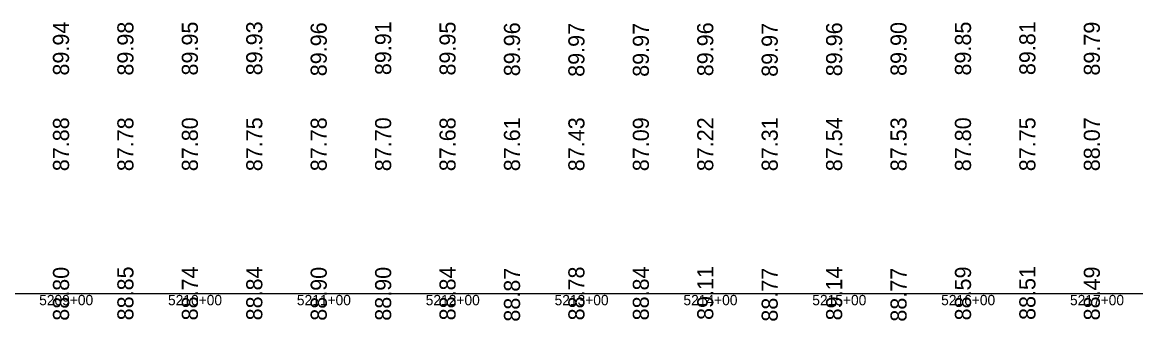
# Model space of a CAD drawing. Extents: x 2147288 to 2220488, y 740833 to 759333.
# Drawn here: x 2203244 to 2204108, y 750062 to 750294 of the extents above; entities that cross this region are included whole.
import ezdxf

# ---------------------------------------------------------------- set-up
doc = ezdxf.new("R2010")
doc.units = 0
for name, color, linetype in [('RD_DDB_Profile_EX', 7, 'Continuous'), ('RD_DDB_StaTX', 7, 'Continuous'), ('RD_DDB_StripGrade', 7, 'Continuous'), ('RD_GPK_Profile_Cell', 7, 'Continuous')]:
    doc.layers.add(name, color=color, linetype=linetype)

msp = doc.modelspace()

# ---------------------------------------------------------------- linework, layer by layer
at = {"layer": 'RD_GPK_Profile_Cell'}
msp.add_line((2198888.28, 750083.43), (2220488.28, 750083.43), dxfattribs=at)

# ---------------------------------------------------------------- texts
at = {"layer": 'RD_DDB_Profile_EX'}
for s, p in [('89.94', (2203280.08, 750252.66)), ('89.98', (2203330.08, 750252.64)), ('89.95', (2203380.08, 750252.69)), ('89.93', (2203430.08, 750252.89)), ('89.96', (2203480.08, 750252.13)), ('89.91', (2203530.08, 750253)), ('89.95', (2203580.08, 750252.69)), ('89.96', (2203630.08, 750252.13)), ('89.97', (2203680.08, 750251.67)), ('89.97', (2203730.08, 750251.67)), ('89.96', (2203780.08, 750252.13)), ('89.97', (2203830.08, 750251.67)), ('89.96', (2203880.08, 750252.13)), ('89.90', (2203930.08, 750252.38)), ('89.85', (2203980.08, 750252.69)), ('89.81', (2204030.08, 750253)), ('89.79', (2204080.08, 750252.64)), ('88.80', (2203280.08, 750062.38)), ('88.85', (2203330.08, 750062.69)), ('88.74', (2203380.08, 750062.66)), ('88.84', (2203430.08, 750062.66)), ('88.90', (2203480.08, 750062.38)), ('88.90', (2203530.08, 750062.38)), ('88.84', (2203580.08, 750062.66)), ('88.87', (2203630.08, 750061.67)), ('88.78', (2203680.08, 750062.64)), ('88.84', (2203730.08, 750062.66)), ('89.11', (2203780.08, 750063)), ('88.77', (2203830.08, 750061.67)), ('89.14', (2203880.08, 750062.66)), ('88.77', (2203930.08, 750061.67)), ('88.59', (2203980.08, 750062.64)), ('88.51', (2204030.08, 750063)), ('88.49', (2204080.08, 750062.64))]:
    msp.add_text(s, height=12.5, rotation=90, dxfattribs=at).set_placement(p)
at = {"layer": 'RD_DDB_StaTX'}
for s, p in [('5209+00', (2203256.88, 750074.43)), ('5209+00', (2203256.88, 750074.43)), ('5209+00', (2203256.88, 750074.43)), ('5210+00', (2203356.88, 750074.43)), ('5210+00', (2203356.88, 750074.43)), ('5210+00', (2203356.88, 750074.43)), ('5211+00', (2203456.88, 750074.43)), ('5211+00', (2203456.88, 750074.43)), ('5211+00', (2203456.88, 750074.43)), ('5212+00', (2203556.88, 750074.43)), ('5212+00', (2203556.88, 750074.43)), ('5212+00', (2203556.88, 750074.43)), ('5213+00', (2203656.88, 750074.43)), ('5213+00', (2203656.88, 750074.43)), ('5213+00', (2203656.88, 750074.43)), ('5214+00', (2203756.88, 750074.43)), ('5214+00', (2203756.88, 750074.43)), ('5214+00', (2203756.88, 750074.43)), ('5215+00', (2203856.88, 750074.43)), ('5215+00', (2203856.88, 750074.43)), ('5215+00', (2203856.88, 750074.43)), ('5216+00', (2203956.88, 750074.43)), ('5216+00', (2203956.88, 750074.43)), ('5216+00', (2203956.88, 750074.43)), ('5217+00', (2204056.88, 750074.43)), ('5217+00', (2204056.88, 750074.43)), ('5217+00', (2204056.88, 750074.43))]:
    msp.add_text(s, height=8, dxfattribs=at).set_placement(p)
at = {"layer": 'RD_DDB_StripGrade'}
for s, p in [('87.88', (2203280.08, 750178.43)), ('87.78', (2203330.08, 750178.43)), ('87.80', (2203380.08, 750178.43)), ('87.75', (2203430.08, 750178.43)), ('87.78', (2203480.08, 750178.43)), ('87.70', (2203530.08, 750178.43)), ('87.68', (2203580.08, 750178.43)), ('87.61', (2203630.08, 750178.43)), ('87.43', (2203680.08, 750178.43)), ('87.09', (2203730.08, 750178.43)), ('87.22', (2203780.08, 750178.43)), ('87.31', (2203830.08, 750178.43)), ('87.54', (2203880.08, 750178.43)), ('87.53', (2203930.08, 750178.43)), ('87.80', (2203980.08, 750178.43)), ('87.75', (2204030.08, 750178.43)), ('88.07', (2204080.08, 750178.43))]:
    msp.add_text(s, height=12.5, rotation=90, dxfattribs=at).set_placement(p)

doc.saveas('drawing.dxf')
